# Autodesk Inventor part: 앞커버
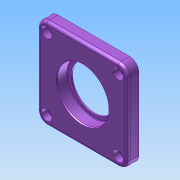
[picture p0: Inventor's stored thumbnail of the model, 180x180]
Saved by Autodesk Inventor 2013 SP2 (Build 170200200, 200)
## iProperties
Created: 2025-06
Part Number: 앞커버
Material: Generic
Document SubType Name: Modeling
Designer: a
Density: 1 g/cm^3
Author: a
변환 표준: STEP AP214IS
전처리기: Build: 200, Release: 2013 SP2 Update 6 - Date: Thu 07/17/2014
전송 단위: 밀리미터
불확실성: 0.01
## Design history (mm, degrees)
node "앞커버1"
node "솔리드1"
node "기준1"
